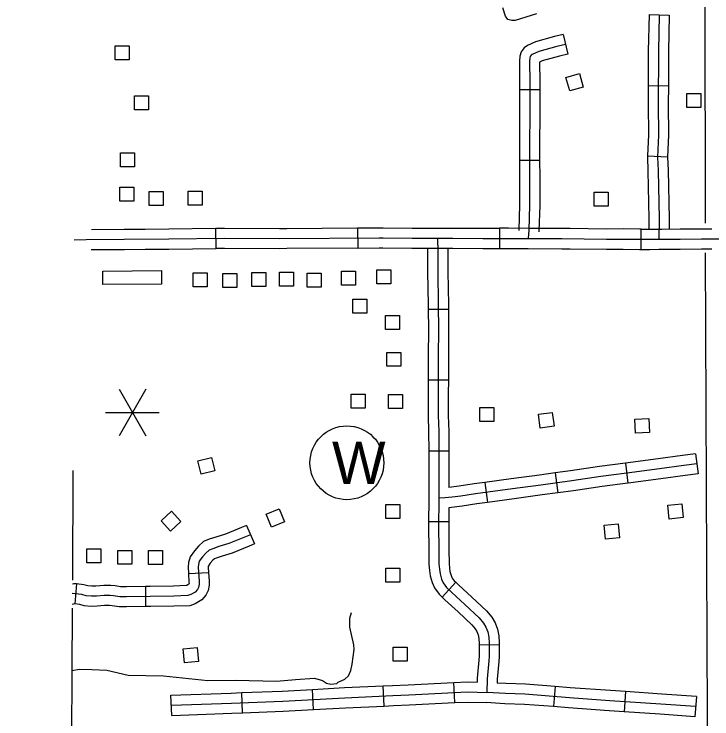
# Model space of a CAD drawing. Extents: x -19 to 366, y -4 to 359.
# Drawn here: x 133.386 to 134.371, y 202.413 to 203.408 of the extents above; entities that cross this region are included whole.
import ezdxf

# ---------------------------------------------------------------- set-up
doc = ezdxf.new("R2010")
doc.units = 0
for name, color, linetype in [('21', 7, 'Continuous'), ('60', 7, 'Continuous'), ('R_Alt Surface', 7, 'Continuous'), ('R_Axis Annot', 7, 'Continuous'), ('R_Border Notes', 7, 'Continuous'), ('R_ROW', 7, 'Continuous'), ('R_ROW Annot', 7, 'Continuous'), ('R_Temp Easement', 7, 'Continuous'), ('Sheet Fence', 7, 'Continuous'), ('T_Vehicle Path Lt Minor', 7, 'Continuous')]:
    doc.layers.add(name, color=color, linetype=linetype)

msp = doc.modelspace()

# ---------------------------------------------------------------- linework, layer by layer
at = {"layer": '21'}
for points in [[(133.52869, 203.34375), (133.52869, 203.36346), (133.54847, 203.36346), (133.54847, 203.34375)], [(134.18403, 203.32409), (134.18942, 203.30512), (134.1704, 203.29972), (134.16501, 203.31868)], [(133.55587, 203.27303), (133.55587, 203.29274), (133.57564, 203.29274), (133.57564, 203.27303)], [(134.33556, 203.27624), (134.33556, 203.29596), (134.35533, 203.29596), (134.35533, 203.27625)], [(133.53654, 203.19244), (133.53654, 203.21216), (133.55631, 203.21216), (133.55631, 203.19244)], [(133.53536, 203.14415), (133.53536, 203.16387), (133.55513, 203.16387), (133.55513, 203.14415)], [(133.5768, 203.13796), (133.5768, 203.15768), (133.59657, 203.15768), (133.59657, 203.13796)], [(133.63177, 203.13868), (133.63177, 203.15839), (133.65154, 203.15839), (133.65154, 203.13868)], [(134.20496, 203.13689), (134.20496, 203.1566), (134.22473, 203.1566), (134.22473, 203.13689)], [(133.51157, 203.02644), (133.51142, 203.04538), (133.59428, 203.04605), (133.59443, 203.02711)], [(133.76067, 203.02397), (133.76067, 203.04368), (133.78045, 203.04368), (133.78045, 203.02397)], [(133.84829, 203.02551), (133.84829, 203.04522), (133.86807, 203.04522), (133.86807, 203.02551)], [(133.89804, 203.02757), (133.89804, 203.04729), (133.91781, 203.04729), (133.91781, 203.02757)], [(133.63893, 203.02308), (133.63893, 203.04279), (133.6587, 203.04279), (133.6587, 203.02308)], [(133.68061, 203.02203), (133.68061, 203.04175), (133.70039, 203.04175), (133.70039, 203.02203)], [(133.72182, 203.02365), (133.72182, 203.04336), (133.74159, 203.04336), (133.74159, 203.02365)], [(133.79979, 203.02263), (133.79979, 203.04234), (133.81957, 203.04234), (133.81957, 203.02263)], [(133.86432, 202.98608), (133.86432, 203.0058), (133.8841, 203.0058), (133.8841, 202.98608)], [(133.91055, 202.96298), (133.91055, 202.98269), (133.93033, 202.98269), (133.93033, 202.96298)], [(133.91234, 202.91096), (133.91234, 202.93067), (133.93211, 202.93067), (133.93211, 202.91096)], [(133.86209, 202.85179), (133.86209, 202.8715), (133.88186, 202.8715), (133.88186, 202.85179)], [(133.91456, 202.8514), (133.91456, 202.87111), (133.93433, 202.87111), (133.93433, 202.8514)], [(134.04356, 202.83294), (134.04356, 202.85265), (134.06333, 202.85265), (134.06333, 202.83294)], [(134.14571, 202.84587), (134.14832, 202.82633), (134.12872, 202.82372), (134.12611, 202.84326)], [(134.28187, 202.83743), (134.28316, 202.81775), (134.26343, 202.81646), (134.26215, 202.83613)], [(133.66462, 202.78242), (133.6694, 202.76329), (133.65022, 202.75849), (133.64544, 202.77762)], [(133.91072, 202.69631), (133.91072, 202.71602), (133.93049, 202.71603), (133.93049, 202.69631)], [(134.3285, 202.71697), (134.33058, 202.69737), (134.31091, 202.69529), (134.30884, 202.71489)], [(133.60825, 202.70629), (133.62157, 202.69176), (133.607, 202.6784), (133.59368, 202.69292)], [(133.7677, 202.69128), (133.74945, 202.68382), (133.74197, 202.70212), (133.76021, 202.70958)], [(134.23881, 202.68846), (134.24045, 202.66881), (134.22075, 202.66717), (134.21911, 202.68681)], [(133.48893, 202.63338), (133.48892, 202.6531), (133.5087, 202.6531), (133.5087, 202.63338)], [(133.53254, 202.63145), (133.53254, 202.65116), (133.55231, 202.65116), (133.55231, 202.63145)], [(133.57567, 202.63104), (133.57566, 202.65075), (133.59544, 202.65075), (133.59544, 202.63104)], [(133.91074, 202.60617), (133.91074, 202.62589), (133.93051, 202.62589), (133.93052, 202.60618)], [(133.62653, 202.49253), (133.62475, 202.51216), (133.64444, 202.51395), (133.64622, 202.49432)], [(133.92111, 202.49485), (133.92111, 202.51456), (133.94088, 202.51456), (133.94088, 202.49485)]]:
    msp.add_lwpolyline(points, close=True, dxfattribs=at)
at = {"layer": '60'}
msp.add_circle((133.85585, 202.77477), 0.05208, dxfattribs=at)
at = {"layer": 'R_Alt Surface'}
for points in [[(133.46927, 202.76368), (133.46842, 202.60886)], [(133.4682, 202.56931), (133.4667, 202.29762)]]:
    msp.add_lwpolyline(points, dxfattribs=at)
at = {"layer": 'R_Axis Annot'}
for points in [[(134.36196, 203.11288), (134.36106, 203.74667)], [(134.36623, 202.0884), (134.36208, 203.0712)]]:
    msp.add_lwpolyline(points, dxfattribs=at)
at = {"layer": 'R_Border Notes'}
msp.add_line((133.47429, 202.60383), (133.47208, 202.57549), dxfattribs=at)
for points in [[(133.47429, 202.60383), (133.47054, 202.60377), (133.46839, 202.60351)], [(133.47208, 202.57549), (133.46823, 202.57458)]]:
    msp.add_lwpolyline(points, dxfattribs=at)
at = {"layer": 'R_ROW'}
for p, q in [((133.67124, 203.07735), (133.67089, 203.10576)), ((133.87095, 203.10628), (133.87117, 203.07787)), ((134.07105, 203.10578), (134.07106, 203.07737)), ((134.27101, 203.07606), (134.27108, 203.10447))]:
    msp.add_line(p, q, dxfattribs=at)
for points in [[(133.49524, 203.10425), (133.54159, 203.10444), (133.57096, 203.10467)], [(133.57096, 203.10467), (133.60447, 203.10494), (133.67089, 203.10576)], [(133.67089, 203.10576), (133.68317, 203.10591), (133.76091, 203.10545), (133.77096, 203.10553)], [(133.77096, 203.10553), (133.87095, 203.10628)], [(133.87095, 203.10628), (133.90153, 203.10651), (133.90707, 203.10641), (133.9479, 203.10606), (133.97109, 203.106)], [(133.97109, 203.106), (133.98374, 203.10597), (134.00522, 203.10621), (134.04764, 203.10577), (134.07105, 203.10578)], [(134.1712, 203.10529), (134.15952, 203.10541), (134.11199, 203.10545), (134.08391, 203.10579), (134.07105, 203.10578)], [(134.27108, 203.10447), (134.26924, 203.10448), (134.24607, 203.10486), (134.22222, 203.10477), (134.1712, 203.10529)], [(134.27108, 203.10447), (134.28085, 203.10445), (134.28315, 203.10446), (134.29617, 203.10451), (134.30019, 203.10453), (134.32611, 203.10481), (134.35606, 203.10507), (134.37103, 203.10508)], [(133.47108, 203.08971), (133.48787, 203.09001), (133.54167, 203.09023), (133.60461, 203.09074), (133.68322, 203.09171), (133.76092, 203.09125), (133.90146, 203.0923), (133.90688, 203.0922), (133.94782, 203.09185), (133.9838, 203.09177)], [(133.9838, 203.09177), (134.00523, 203.092), (134.04757, 203.09157), (134.08383, 203.09158), (134.1119, 203.09125)], [(134.1119, 203.09125), (134.15944, 203.09121), (134.22218, 203.09057), (134.24598, 203.09065), (134.26911, 203.09027), (134.28085, 203.09025), (134.2832, 203.09026), (134.29622, 203.09031)], [(134.29622, 203.09031), (134.3003, 203.09033), (134.32625, 203.0906), (134.35613, 203.09087), (134.39244, 203.09089), (134.41245, 203.09111), (134.4309, 203.09099)], [(133.49508, 203.07584), (133.54176, 203.07603), (133.57119, 203.07627)], [(133.57119, 203.07627), (133.60476, 203.07654), (133.67124, 203.07735)], [(133.77117, 203.07712), (133.76093, 203.07704), (133.68326, 203.0775), (133.67124, 203.07735)], [(133.87117, 203.07787), (133.77117, 203.07712)], [(133.87117, 203.07787), (133.90138, 203.0781), (133.90669, 203.078), (133.94774, 203.07765), (133.97102, 203.07759)], [(133.97102, 203.07759), (133.98386, 203.07756), (134.00523, 203.0778), (134.0475, 203.07736), (134.07106, 203.07737)], [(134.07106, 203.07737), (134.08375, 203.07738), (134.11181, 203.07705), (134.15936, 203.077), (134.17091, 203.07688)], [(134.17091, 203.07688), (134.22213, 203.07636), (134.24589, 203.07645), (134.26897, 203.07607), (134.27101, 203.07606)], [(134.27101, 203.07606), (134.28086, 203.07604), (134.28325, 203.07605), (134.29628, 203.07611), (134.3004, 203.07612), (134.32639, 203.0764), (134.3562, 203.07666), (134.37105, 203.07667)]]:
    msp.add_lwpolyline(points, dxfattribs=at)
at = {"layer": 'R_ROW Annot'}
for p, q in [((134.28251, 203.40749), (134.31091, 203.40683)), ((134.16128, 203.37924), (134.16763, 203.35155)), ((134.28118, 203.30721), (134.30959, 203.30714)), ((134.09967, 203.30181), (134.12808, 203.30187)), ((134.28001, 203.20787), (134.30839, 203.20655)), ((134.09945, 203.20178), (134.12785, 203.2019)), ((133.97073, 202.9917), (133.99914, 202.99186)), ((133.97068, 202.89188), (133.99909, 202.89168)), ((133.97132, 202.79176), (133.99973, 202.79182)), ((134.34802, 202.78746), (134.35175, 202.7593)), ((134.24912, 202.77401), (134.25247, 202.7458)), ((134.14982, 202.76047), (134.15363, 202.73232)), ((134.05077, 202.74708), (134.05448, 202.71892)), ((133.71408, 202.68629), (133.72529, 202.66018)), ((133.97123, 202.69191), (133.99964, 202.69167)), ((133.63223, 202.61835), (133.66059, 202.62009)), ((133.99019, 202.58514), (134.00943, 202.60604)), ((133.57149, 202.60016), (133.57181, 202.57175)), ((134.0424, 202.51787), (134.07081, 202.51819)), ((133.90841, 202.43135), (133.90719, 202.45973)), ((134.00841, 202.43615), (134.00696, 202.46452)), ((134.14975, 202.45881), (134.14749, 202.43049)), ((133.70857, 202.42188), (133.70749, 202.45027)), ((133.80872, 202.42647), (133.80712, 202.45483)), ((134.24929, 202.45169), (134.24744, 202.42334)), ((133.60862, 202.41817), (133.60758, 202.44656)), ((134.34919, 202.44465), (134.34704, 202.41633))]:
    msp.add_line(p, q, dxfattribs=at)
for points in [[(134.28251, 203.40749), (134.28131, 203.35594), (134.28118, 203.30721)], [(134.29671, 203.40716), (134.29551, 203.35575), (134.29532, 203.281), (134.29561, 203.23749), (134.29414, 203.20601), (134.29503, 203.18754), (134.2964, 203.11919), (134.29622, 203.09031)], [(134.31091, 203.40683), (134.30971, 203.35557), (134.30959, 203.30714)], [(134.16128, 203.37924), (134.14887, 203.3764), (134.12194, 203.36889), (134.11075, 203.36381), (134.10593, 203.36071), (134.1016, 203.35483), (134.09995, 203.34891), (134.09946, 203.34153), (134.09964, 203.31234), (134.09967, 203.30181)], [(134.16446, 203.3654), (134.15236, 203.36263), (134.12681, 203.3555), (134.11756, 203.3513), (134.11581, 203.35018), (134.11459, 203.34851), (134.11403, 203.34651), (134.11367, 203.34111), (134.11385, 203.3124), (134.1139, 203.28773), (134.11388, 203.26555), (134.11354, 203.22576), (134.11376, 203.17848), (134.11376, 203.13822), (134.11276, 203.10294), (134.1119, 203.09125)], [(134.16763, 203.35155), (134.15586, 203.34885), (134.13168, 203.34211), (134.12788, 203.34039), (134.12805, 203.31246), (134.12808, 203.30187)], [(134.28118, 203.30721), (134.28111, 203.28097), (134.2814, 203.23777), (134.28001, 203.20787)], [(134.30959, 203.30714), (134.30952, 203.28103), (134.30982, 203.2372), (134.30839, 203.20655)], [(134.09967, 203.30181), (134.0997, 203.28772), (134.09968, 203.26562), (134.09934, 203.22578), (134.09945, 203.20178)], [(134.12808, 203.30187), (134.12811, 203.28774), (134.12809, 203.26548), (134.12775, 203.22573), (134.12785, 203.2019)], [(134.28001, 203.20787), (134.27992, 203.206), (134.28083, 203.18706), (134.28219, 203.11909), (134.2821, 203.10446)], [(134.30839, 203.20655), (134.30836, 203.20602), (134.30923, 203.18802), (134.3106, 203.11929), (134.31052, 203.10464)], [(134.09945, 203.20178), (134.09955, 203.17845), (134.09955, 203.13842), (134.09857, 203.10366), (134.09851, 203.10289)], [(134.12785, 203.2019), (134.12796, 203.17851), (134.12796, 203.13802), (134.12695, 203.10222), (134.12685, 203.10082)], [(133.9838, 203.09177), (133.98402, 203.07258), (133.984, 203.0449), (133.9849, 202.99759), (133.9851, 202.96269), (133.98484, 202.92567), (133.98491, 202.89507), (133.98474, 202.87161), (133.9848, 202.84135), (133.98547, 202.81894), (133.98555, 202.77699), (133.98571, 202.75423), (133.98567, 202.72498)], [(133.96982, 203.0776), (133.9698, 203.04477), (133.9707, 202.99741), (133.97073, 202.9917)], [(133.99823, 203.07772), (133.99821, 203.04503), (133.99911, 202.99776), (133.99914, 202.99186)], [(133.97073, 202.9917), (133.9709, 202.9627), (133.97064, 202.92571), (133.97071, 202.89511), (133.97068, 202.89188)], [(133.99914, 202.99186), (133.99931, 202.96268), (133.99905, 202.92564), (133.99911, 202.89503), (133.99909, 202.89168)], [(133.97068, 202.89188), (133.97054, 202.87165), (133.97059, 202.84112), (133.97127, 202.81871), (133.97132, 202.79176)], [(133.99909, 202.89168), (133.99894, 202.87157), (133.999, 202.84158), (133.99968, 202.81917), (133.99973, 202.79182)], [(133.97132, 202.79176), (133.97134, 202.77693), (133.97151, 202.75419), (133.97146, 202.72497), (133.97147, 202.7216), (133.97123, 202.69191)], [(133.99973, 202.79182), (133.99975, 202.77706), (133.99992, 202.75427), (133.9999, 202.73978)], [(134.34802, 202.78746), (134.32953, 202.78501), (134.29496, 202.78036), (134.24912, 202.77401), (134.24912, 202.77401)], [(134.34988, 202.77338), (134.33141, 202.77093), (134.29688, 202.76628), (134.25093, 202.75993), (134.21423, 202.75556), (134.17354, 202.74935), (134.1295, 202.74339), (134.08983, 202.7379), (134.0374, 202.731), (134.01654, 202.72779), (134.00423, 202.72605), (133.99395, 202.72539), (133.98567, 202.72498)], [(134.24912, 202.77401), (134.21232, 202.76963), (134.17151, 202.76341), (134.14982, 202.76047)], [(134.14982, 202.76047), (134.12757, 202.75746), (134.08792, 202.75197), (134.05077, 202.74708)], [(134.35175, 202.7593), (134.33329, 202.75685), (134.2988, 202.75221), (134.25274, 202.74584), (134.25247, 202.7458)], [(134.05077, 202.74708), (134.0354, 202.74506), (134.01446, 202.74184), (133.9999, 202.73978)], [(134.25247, 202.7458), (134.21614, 202.74148), (134.17556, 202.73529), (134.15363, 202.73232)], [(134.15363, 202.73232), (134.13142, 202.72932), (134.09173, 202.72382), (134.05448, 202.71892)], [(133.98567, 202.72498), (133.98568, 202.72156), (133.98538, 202.68572), (133.98556, 202.6516), (133.98578, 202.63217), (133.98637, 202.62454), (133.98741, 202.61821), (133.98953, 202.61071), (133.99193, 202.6051), (133.9966, 202.59854), (134.00384, 202.59188), (134.02236, 202.5746), (134.04267, 202.55595), (134.04872, 202.5484), (134.05216, 202.54283), (134.05459, 202.53603), (134.05619, 202.52868), (134.05658, 202.52019), (134.05668, 202.51143), (134.05662, 202.50179), (134.05622, 202.4952), (134.054, 202.46995), (134.05333, 202.45035)], [(134.05448, 202.71892), (134.03941, 202.71694), (134.01862, 202.71374), (133.9998, 202.71107)], [(133.9998, 202.71107), (133.99964, 202.69167)], [(133.71408, 202.68629), (133.70723, 202.68335), (133.68443, 202.67413), (133.67083, 202.66999), (133.6616, 202.66675), (133.6536, 202.66358), (133.64658, 202.65713), (133.64079, 202.6507), (133.63473, 202.64208), (133.63217, 202.63408), (133.63168, 202.62735), (133.63223, 202.61835)], [(133.97123, 202.69191), (133.97118, 202.68574), (133.97135, 202.65148), (133.97159, 202.63155), (133.97225, 202.62284), (133.97353, 202.61511), (133.97611, 202.60597), (133.97947, 202.59811), (133.98589, 202.5891), (133.99019, 202.58514)], [(133.99964, 202.69167), (133.99959, 202.6857), (133.99976, 202.65172), (133.99998, 202.6328), (134.00049, 202.62624), (134.0013, 202.62131), (134.00295, 202.61545), (134.00439, 202.6121), (134.00731, 202.60799), (134.00943, 202.60604)], [(133.71968, 202.67324), (133.71269, 202.67023), (133.68917, 202.66072), (133.67526, 202.65649), (133.66656, 202.65343), (133.66127, 202.65134), (133.65668, 202.64713), (133.65192, 202.64183), (133.6476, 202.63569), (133.64622, 202.63135), (133.64591, 202.62727), (133.64716, 202.60699), (133.64727, 202.60335), (133.64634, 202.59881), (133.64494, 202.59576), (133.64183, 202.59224), (133.63571, 202.58862), (133.63146, 202.5872), (133.6114, 202.58659), (133.5784, 202.58603), (133.54485, 202.58566), (133.53542, 202.58559), (133.5266, 202.58682), (133.52186, 202.58754), (133.51329, 202.5875), (133.50238, 202.58653), (133.4953, 202.58632), (133.48777, 202.58695), (133.48173, 202.5887), (133.46831, 202.5902)], [(133.72529, 202.66018), (133.71816, 202.65712), (133.69391, 202.64732), (133.67968, 202.64298), (133.67153, 202.64012), (133.66894, 202.6391), (133.66679, 202.63712), (133.66305, 202.63296), (133.66047, 202.6293), (133.66026, 202.62863), (133.66015, 202.62718), (133.66059, 202.62009)], [(133.63223, 202.61835), (133.63297, 202.60634), (133.63302, 202.60458), (133.6328, 202.60347), (133.63266, 202.60332), (133.62978, 202.60161), (133.62895, 202.60133), (133.61106, 202.60079), (133.5782, 202.60023), (133.57149, 202.60016)], [(133.66059, 202.62009), (133.66135, 202.60764), (133.66152, 202.60212), (133.65993, 202.59436), (133.65698, 202.58793), (133.65099, 202.58115), (133.64164, 202.57562), (133.63398, 202.57306), (133.61173, 202.57239), (133.5786, 202.57183), (133.57181, 202.57175)], [(134.00943, 202.60604), (134.01349, 202.6023), (134.032, 202.58502), (134.05307, 202.56568), (134.06036, 202.5566), (134.06503, 202.54901), (134.06828, 202.53994), (134.07032, 202.53053), (134.07078, 202.5206), (134.07081, 202.51819)], [(133.57149, 202.60016), (133.54472, 202.59986), (133.53636, 202.5998), (133.52864, 202.60088), (133.5229, 202.60175), (133.51262, 202.6017), (133.50153, 202.60071), (133.49568, 202.60054), (133.49037, 202.60098), (133.48452, 202.60268), (133.47429, 202.60383)], [(133.99019, 202.58514), (133.99418, 202.58146), (134.01271, 202.56417), (134.03227, 202.54622), (134.03709, 202.5402), (134.03929, 202.53664), (134.04091, 202.53211), (134.04205, 202.52683), (134.04238, 202.51978), (134.0424, 202.51787)], [(133.57181, 202.57175), (133.54497, 202.57145), (133.53448, 202.57138), (133.52455, 202.57277), (133.52083, 202.57333), (133.51395, 202.5733), (133.50322, 202.57234), (133.49492, 202.57209), (133.48518, 202.57291), (133.47894, 202.57472), (133.47208, 202.57549)], [(134.0424, 202.51787), (134.04248, 202.51139), (134.04241, 202.50226), (134.04205, 202.49625), (134.03981, 202.47081), (134.03962, 202.46503)], [(134.07081, 202.51819), (134.07089, 202.51146), (134.07082, 202.50132), (134.07039, 202.49416), (134.06818, 202.46908), (134.068, 202.46374)], [(133.80712, 202.45483), (133.85235, 202.45738), (133.90719, 202.45973)], [(133.90719, 202.45973), (133.92029, 202.46029), (133.94247, 202.46124), (134.00696, 202.46452)], [(134.00696, 202.46452), (134.02616, 202.4655), (134.03962, 202.46503)], [(134.14975, 202.45881), (134.10796, 202.46215), (134.0802, 202.46305), (134.068, 202.46374)], [(134.24929, 202.45169), (134.22787, 202.45309), (134.17098, 202.45711), (134.14975, 202.45881)], [(133.60758, 202.44656), (133.6925, 202.4497), (133.70749, 202.45027)], [(133.6081, 202.43237), (133.69303, 202.4355), (133.76533, 202.43825), (133.85305, 202.44319), (133.9209, 202.4461), (133.94313, 202.44705), (134.02628, 202.45128), (134.05333, 202.45035)], [(133.70749, 202.45027), (133.76466, 202.45244), (133.80712, 202.45483)], [(134.34812, 202.43049), (134.29919, 202.43419), (134.22691, 202.43891), (134.16992, 202.44295), (134.10717, 202.44796), (134.07957, 202.44886), (134.05333, 202.45035)], [(134.34919, 202.44465), (134.30019, 202.44836), (134.24929, 202.45169)], [(134.00841, 202.43615), (134.0264, 202.43706), (134.05284, 202.43615)], [(133.80872, 202.42647), (133.85376, 202.42901), (133.90841, 202.43135)], [(133.90841, 202.43135), (133.9215, 202.43191), (133.94379, 202.43286), (134.00841, 202.43615)], [(134.14749, 202.43049), (134.10637, 202.43378), (134.07894, 202.43467), (134.05252, 202.43617)], [(134.24744, 202.42334), (134.22594, 202.42474), (134.16885, 202.42879), (134.14749, 202.43049)], [(133.60862, 202.41817), (133.69357, 202.42131), (133.70857, 202.42188)], [(133.70857, 202.42188), (133.766, 202.42406), (133.80872, 202.42647)], [(134.34704, 202.41633), (134.29819, 202.42002), (134.24744, 202.42334)]]:
    msp.add_lwpolyline(points, dxfattribs=at)
at = {"layer": 'R_Temp Easement'}
for points in [[(134.12349, 203.40855), (134.09335, 203.39903), (134.08843, 203.39896), (134.08311, 203.4004), (134.07963, 203.40528), (134.07604, 203.41699)], [(133.46771, 202.48174), (133.47869, 202.48325), (133.496, 202.48317), (133.51683, 202.48195), (133.54722, 202.47517), (133.5972, 202.47397), (133.65976, 202.46764), (133.69874, 202.46781), (133.75668, 202.46635), (133.78351, 202.469), (133.81037, 202.47052), (133.82139, 202.46726), (133.82713, 202.46354), (133.83321, 202.46211), (133.8419, 202.46299), (133.84376, 202.46492), (133.85316, 202.46922), (133.85801, 202.47384), (133.8613, 202.48148), (133.86343, 202.49061), (133.86615, 202.51114), (133.86567, 202.51796), (133.85999, 202.54254), (133.86017, 202.55544), (133.86232, 202.56343)]]:
    msp.add_lwpolyline(points, dxfattribs=at)
at = {"layer": 'Sheet Fence'}
for points in [[(139.44064, 1.53154), (139.25106, 10.14733), (139.06082, 18.76327), (138.86992, 27.37935), (138.67836, 35.99557), (138.48613, 44.61194), (138.29325, 53.22845), (138.09971, 61.84511), (137.9055, 70.46191), (137.71065, 79.07885), (137.51513, 87.69595), (137.31896, 96.31318), (137.12214, 104.93057), (136.92466, 113.54809), (136.72653, 122.16577), (136.52775, 130.78359), (136.32832, 139.40156), (136.12824, 148.01968), (135.9275, 156.63794), (135.72612, 165.25636), (135.5241, 173.87492), (135.32143, 182.49362), (135.11811, 191.11248), (134.91415, 199.73149), (134.70954, 208.35064), (134.50429, 216.96995), (134.2984, 225.5894), (134.09187, 234.209), (133.8847, 242.82876), (133.6769, 251.44866), (133.46845, 260.06872), (133.25937, 268.68892), (133.04965, 277.30928), (132.8393, 285.92978), (132.62831, 294.55044), (132.41669, 303.17125), (132.20444, 311.79221), (131.99156, 320.41333), (131.77805, 329.0346), (131.56391, 337.65601), (131.34914, 346.27759)], [(0, 198.13258), (7.10141, 198.13701), (14.2028, 198.15029), (21.30418, 198.17244), (28.40552, 198.20345), (35.50682, 198.24331), (42.60806, 198.29203), (49.70923, 198.34961), (56.81033, 198.41605), (63.91134, 198.49135), (71.01225, 198.5755), (78.11305, 198.66852), (85.21373, 198.77039), (92.31428, 198.88112), (99.41468, 199.0007), (106.51492, 199.12915), (113.61501, 199.26645), (120.71491, 199.4126), (127.81463, 199.56762), (134.91415, 199.73149), (142.01345, 199.90421), (149.11254, 200.0858), (156.2114, 200.27623), (163.31001, 200.47553), (170.40837, 200.68367), (177.50646, 200.90068), (184.60427, 201.12653), (191.7018, 201.36125), (198.79903, 201.60481), (205.89596, 201.85723), (212.99256, 202.1185), (220.08883, 202.38862), (227.18475, 202.6676), (234.28033, 202.95542), (241.37554, 203.2521), (248.47037, 203.55763), (255.56482, 203.87201), (262.65887, 204.19524), (269.75251, 204.52732), (276.84573, 204.86824), (283.93852, 205.21802), (291.03086, 205.57664), (298.12276, 205.94411), (305.21419, 206.32042), (312.30515, 206.70559), (319.39562, 207.09959), (326.48559, 207.50244), (333.57505, 207.91414), (340.664, 208.33468)]]:
    msp.add_spline(points, degree=3, dxfattribs=at)
at = {"layer": 'T_Vehicle Path Lt Minor'}
for p, q in [((133.57212, 202.87857), (133.53424, 202.81296)), ((133.53424, 202.87857), (133.57212, 202.81296)), ((133.5153, 202.84577), (133.59106, 202.84577))]:
    msp.add_line(p, q, dxfattribs=at)

# ---------------------------------------------------------------- texts
at = {"layer": '60'}
msp.add_text('W', height=0.06, dxfattribs=at).set_placement((133.83482, 202.74477))

doc.saveas('drawing.dxf')
